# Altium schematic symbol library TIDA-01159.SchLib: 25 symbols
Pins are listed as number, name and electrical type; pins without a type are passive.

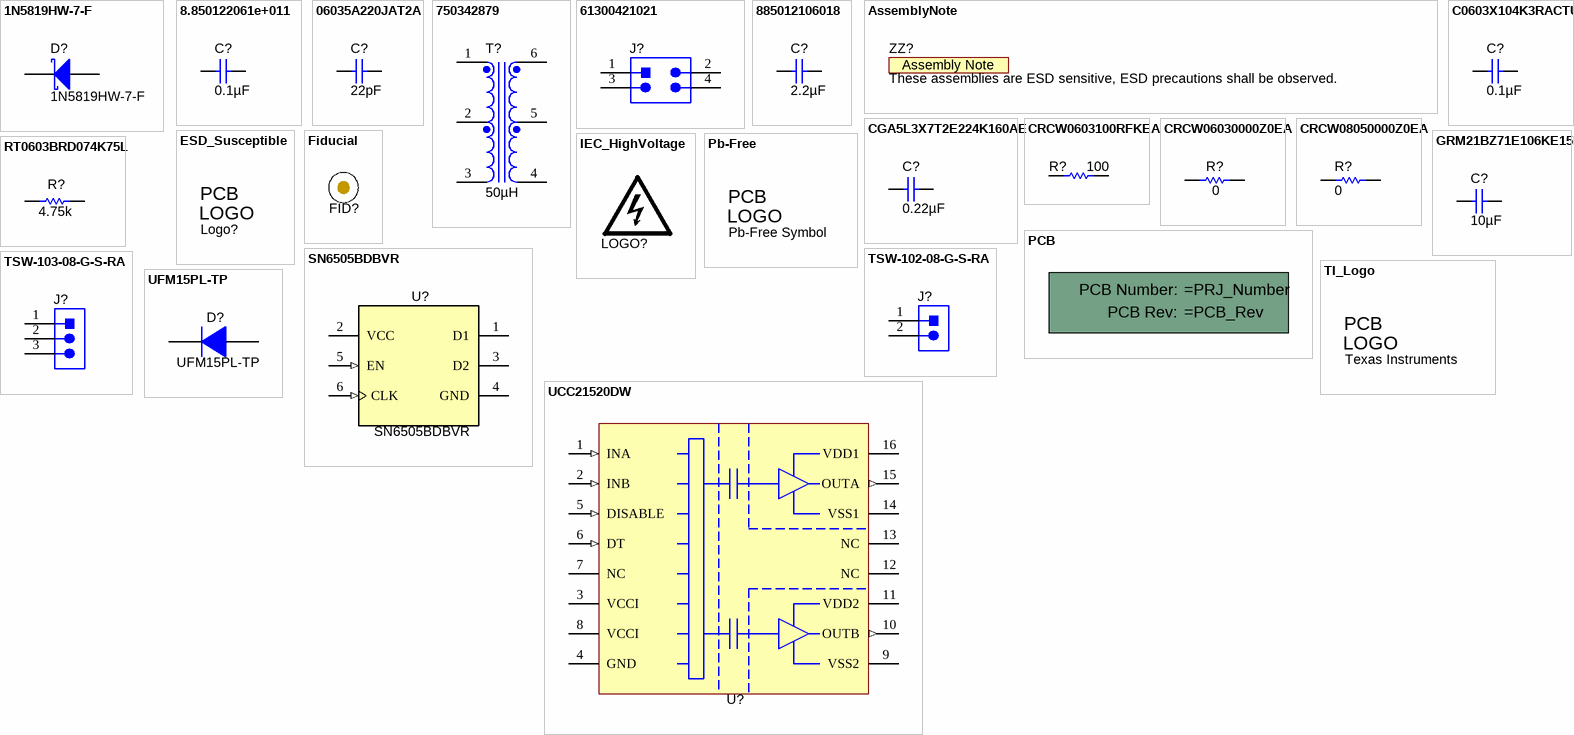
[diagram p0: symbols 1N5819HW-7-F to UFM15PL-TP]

## 1N5819HW-7-F
designator D?
Diode, Schottky, 40 V, 1 A, SOD-123; Manufacturer: Diodes Inc.; U/M: EA; Vf_V: 0.45; Value: 40V; Value1: 1A; Value2: 0.45V; Io_A: 1; Vr_V: 40; TJmax_C: 125; SizeAreaWB_mm2: 13.095; SizeArea_mm2: 6.545; SizeX_mm: 3.85; SizeY_mm: 1.7; SizeZ_mm: 1.35; AEC Category: Q101
signal-integrity model Diode
simulation model DI_1N5819HW
footprint SOD-123
pins: 1 K, 2 A

## 8.850122061e+011
designator C?  ValueDisplayed: 0.1µF  (hidden comment: 8.850122061e+011)
CAP, CERM, 0.1 µF, 50 V, +/- 10%, X7R, 0603; Manufacturer: Wurth Elektronik; Polarized: N; CompType: Capacitor; Value: 0.1uF; U/M: EA; Cap_F: 0.0000001; Tolerance_%: 10; Value1: Unknown; VDC_V: 50; Value2: 50V; TaMin_C: -55; TaMax_C: 125; Cap_Case: 0603; SizeArea_mm2: 1.28; SizeAreaWB_mm2: 4.68; SizeX_mm: 1.6; SizeY_mm: 0.8; SizeZ_mm: 1; AEC Category: Q200
signal-integrity model Cap
simulation model Cap
footprint 0603
footprint 0603M
footprint 0603L
footprint 0603_HV
footprint 0603S
pins: 1, 2

## 06035A220JAT2A
designator C?  ValueDisplayed: 22pF  (hidden comment: 06035A220JAT2A)
CAP, CERM, 22 pF, 50 V, +/- 5%, C0G/NP0, 0603; Manufacturer: AVX; Polarized: N; CompType: Capacitor; Value: 22pF; U/M: EA; Cap_F: 0.000000000022; Tolerance_%: 5; ESR_ohm: 0.259; Value1: 0.259 ohm; VDC_V: 50; Value2: 50V; TaMin_C: -55; TaMax_C: 125; Cap_Case: 0603; SizeArea_mm2: 1.28; SizeAreaWB_mm2: 4.68; SizeX_mm: 1.6; SizeY_mm: 0.8; SizeZ_mm: 1; AEC Category: Q200
signal-integrity model Cap
simulation model Cap
footprint 0603
footprint 0603M
footprint 0603L
footprint 0603_HV
footprint 0603S
pins: 1, 2

## 750342879
designator T?  ValueDisplayed: 50µH  (hidden comment: 750342879)
Transformer, 50 uH, SMT; Manufacturer: Wurth Elektronik; SymbolCreator: Altium; Value: 50uH; Lp: 50
footprint Wurth_750342879
pins: 1, 2, 3, 4, 5, 6

## 61300421021
designator J?  (value not drawn)
Header, 2.54mm, 2x2, Gold, R/A, TH; Manufacturer: Wurth Elektronik; SymbolCreator: a0412235; Pitch_mm: 2.54; Gender: Male; Shrouded: N; Row_Count: 2
footprint Wurth_61300421021
pins: 1, 2, 3, 4

## 885012106018
designator C?  ValueDisplayed: 2.2µF  (hidden comment: 885012106018)
CAP, CERM, 2.2 µF, 16 V, +/- 20%, X5R, 0603; Manufacturer: Wurth Elektronik; Polarized: N; CompType: Capacitor; Value: 2.2uF; U/M: EA; Cap_F: 0.0000022; Tolerance_%: 20; Value1: Unknown; VDC_V: 16; Value2: 16V; TaMin_C: -55; TaMax_C: 85; Cap_Case: 0603; SizeArea_mm2: 1.28; SizeAreaWB_mm2: 4.68; SizeX_mm: 1.6; SizeY_mm: 0.8; SizeZ_mm: 1; AEC Category: Q200
signal-integrity model Cap
simulation model Cap
footprint 0603 (0603 from SM-752 data)
footprint 0603M
footprint 0603L
footprint 0603_HV
footprint 0603S
pins: 1, 2

## AssemblyNote
designator ZZ?, comment These assemblies are ESD sensitive, ESD precautions shall be observed.  (no BOM)
SymbolCreator: codlsc; CompType: AssemblyNote
footprint AssemblyNote

## C0603X104K3RACTU
designator C?  ValueDisplayed: 0.1µF  (hidden comment: C0603X104K3RACTU)
CAP, CERM, 0.1 µF, 25 V, +/- 10%, X7R, 0603; Manufacturer: Kemet; Polarized: N; CompType: Capacitor; Value: 0.1uF; U/M: EA; Cap_F: 0.0000001; Tolerance_%: 10; Value1: Unknown; VDC_V: 25; Value2: 25V; TaMin_C: -55; TaMax_C: 125; Cap_Case: 0603
signal-integrity model Cap
simulation model Cap
footprint 0603
footprint 0603M
footprint 0603L
footprint 0603_HV
footprint 0603S
pins: 1, 2

## CGA5L3X7T2E224K160AE
designator C?  ValueDisplayed: 0.22µF  (hidden comment: CGA5L3X7T2E224K160AE)
CAP, CERM, 0.22 µF, 250 V, +/- 10%, X7T, 1206; Manufacturer: TDK; Polarized: N; CompType: Capacitor; Value: 0.22uF; U/M: EA; Cap_F: 0.00000022; Tolerance_%: 10; Value1: Unknown; VDC_V: 250; Value2: 250V; TaMin_C: -55; TaMax_C: 125; Cap_Case: 1206
signal-integrity model Cap
simulation model Cap
footprint 1206
footprint 1206M
footprint 1206L
pins: 1, 2

## CRCW0603100RFKEA
designator R?  ValueDisplayed: 100  (hidden comment: CRCW0603100RFKEA)
RES, 100, 1%, 0.1 W, 0603; Manufacturer: Vishay-Dale; CompType: Resistor; Value: 100; Value_Code: 100R; Tolerance_%: 1; Power_W: 0.1; Value2: 0.1W; VDC_V: 75; TempCo: 100 ppm/C; EIA_Code: E96; U/M: EA
signal-integrity model Resistor
simulation model Resistor
footprint 0603
footprint 0603M
footprint 0603L
footprint 0603_HV
footprint 0603S
pins: 1, 2

## CRCW06030000Z0EA
designator R?  ValueDisplayed: 0  (hidden comment: CRCW06030000Z0EA)
RES, 0, 5%, 0.1 W, 0603; Manufacturer: Vishay-Dale; CompType: Resistor; Value: 0; Value_Code: 0000; Tolerance_%: 5; Power_W: 0.1; Value2: 0.1W; VDC_V: 75; TempCo: 200 ppm/C; EIA_Code: E24; U/M: EA
signal-integrity model Resistor
simulation model Resistor
footprint 0603
footprint 0603M
footprint 0603L
footprint 0603_HV
footprint 0603S
pins: 1, 2

## CRCW08050000Z0EA
designator R?  ValueDisplayed: 0  (hidden comment: CRCW08050000Z0EA)
RES, 0, 5%, 0.125 W, 0805; Manufacturer: Vishay-Dale; CompType: Resistor; Value: 0; Value_Code: 0000; Tolerance_%: 5; Power_W: 0.125; Value2: 0.125W; VDC_V: 150; TempCo: 200 ppm/C; EIA_Code: E24; U/M: EA; AEC Category: Q200
signal-integrity model Resistor
simulation model Resistor
footprint 0805_HV
footprint 0805_HV1
footprint 0805
footprint 0805M
pins: 1, 2

## ESD_Susceptible
designator Logo?, comment ESD Susceptible  (value not drawn)  (no BOM)
ESD Susceptible Symbol; SymbolCreator: a0412235
footprint ESD_Overlay_Large
footprint ESD_Overlay_Medium
footprint ESD_Overlay_Small

## Fiducial
designator FID?  (value not drawn)
Fiducial mark.  There is nothing to buy or mount.; SymbolCreator: codlsc
footprint Fiducial10-30
footprint Fiducial10-20
footprint Fiducial15-30
footprint Fiducial20-40
footprint Fiducial6.4-20

## GRM21BZ71E106KE15L
designator C?  ValueDisplayed: 10µF  (hidden comment: GRM21BZ71E106KE15L)
CAP, CERM, 10 µF, 25 V, +/- 10%, X7R, 0805; Manufacturer: MuRata; Polarized: N; CompType: Capacitor; Value: 10uF; U/M: EA; Cap_F: 0.00001; Tolerance_%: 10; Value1: Unknown; VDC_V: 25; Value2: 25V; TaMin_C: -55; TaMax_C: 125; Cap_Case: 0805; SizeArea_mm2: 2.5; SizeAreaWB_mm2: 6.75; SizeX_mm: 2; SizeY_mm: 1.25; SizeZ_mm: 1.45; AEC Category: Q200
signal-integrity model Cap
simulation model Cap
footprint 0805_HV
footprint 0805_HV1
footprint 0805
footprint 0805M
footprint 0805L
pins: 1, 2

## IEC_HighVoltage
designator LOGO?, comment DANGER HIGH VOLTAGE  (value not drawn)  (no BOM)
IEC 61010-1 High Voltage Warning; SymbolCreator: a0412235
footprint IEC_HighVoltage_Large
footprint IEC_HighVoltage_Medium
footprint IEC_HighVoltage_Small

## Pb-Free
designator Logo?, comment Pb-Free Symbol  (no BOM)
SymbolCreator: a0412235
footprint Pb-Free_Overlay_Medium
footprint Pb-Free_Overlay_Small

## PCB
designator !PCB?, comment Printed Circuit Board  (value not drawn)  (mechanical)
Manufacturer: Any; SymbolCreator: a0412235; CompType: PCB
1 alternate drawing of the same symbol

## RT0603BRD074K75L
designator R?  ValueDisplayed: 4.75k  (hidden comment: RT0603BRD074K75L)
RES, 4.75 k, 0.1%, 0.1 W, 0603; Manufacturer: Yageo America; CompType: Resistor; Value: 4.75k; Res_ohm: 4750; Value_Code: 4k75; Tolerance_%: 0.1; Value2: 0.1W; VDC_V: 75; TempCo: 25 ppm/C; EIA_Code: E192; U/M: EA
signal-integrity model Resistor
simulation model Resistor
footprint 0603
footprint 0603M
footprint 0603L
footprint 0603_HV
footprint 0603S
pins: 1, 2

## SN6505BDBVR
designator U?
LOW-NOISE 1A TRANSFORMER DRIVERS FOR ISOLATED POWER SUPPLIES, DBV0006A; Alternate PartNumber: SN6505BDBVT; Manufacturer: Texas Instruments; SymbolCreator: Altium; SizeArea_mm2: 8.12; SizeAreaWB_mm2: 14.82; SizeX_mm: 2.8; SizeY_mm: 2.9; SizeZ_mm: 1.45; CompType: IC; U/M: EA
footprint DBV0006A_N
footprint DBV0006A_M
footprint DBV0006A_L
pins: 1 D1 (oc), 2 VCC (power), 3 D2 (oc), 4 GND (power), 5 EN (in), 6 CLK (in)
1 alternate drawing of the same symbol

## TI_Logo
designator Logo?, comment Texas Instruments  (no BOM)
Texas Instrument Corporate Signature; SymbolCreator: codlsc
footprint TI_Stacked_SolderMask_Medium
footprint TI_Stacked_SolderMask_Small
footprint TI_Stacked_Overlay_Medium
footprint TI_Stacked_Overlay_Small
footprint TI_Horizontal_SolderMask_Medium
footprint TI_Horizontal_SolderMask_Small
footprint TI_Horizontal_Overlay_Medium
footprint TI_Horizontal_Overlay_Small
footprint TI_Symbol_SolderMask_Small
footprint TI_Symbol_Overlay_Medium
footprint TI_Symbol_Overlay_Small
footprint TI_Symbol_SolderMask_Medium

## TSW-102-08-G-S-RA
designator J?  (value not drawn)
Header, 100mil, 2x1, Gold, R/A, TH; Manufacturer: Samtec; SymbolCreator: a0412235; Pitch_mm: 2.54; Gender: Male; Shrouded: N; Row_Count: 1; Current_A: 6.3; Voltage_V: 550; Cert_CSA: Y
footprint TSW-102-08-G-S-RA
pins: 1, 2
1 alternate drawing of the same symbol

## TSW-103-08-G-S-RA
designator J?  (value not drawn)
Header, 100mil, 3x1, Gold, R/A, TH; Manufacturer: Samtec; SymbolCreator: a0799628; Pitch_mm: 2.54; Gender: Male; Shrouded: N; Row_Count: 1; Current_A: 6.3; Voltage_V: 550; Cert_CSA: Y
footprint TSW-103-08-G-S-RA
pins: 1, 2, 3
3 alternate drawings of the same symbol

## UCC21520DW
designator U?  (value not drawn)
4A/6A, 5KVrms Dual Isolated-channel Universal Gate Driver, DW0016A; Manufacturer: Texas Instruments; SymbolCreator: a0799628; CompType: IC; U/M: EA
footprint DW0016A_N
footprint DW0016A_M
footprint DW0016A_L
pins: 1 INA (in), 2 INB (in), 3 VCCI (power), 4 GND (power), 5 DISABLE (in), 6 DT (in), 7 NC, 8 VCCI (power), 9 VSS2 (power), 10 OUTB (out), 11 VDD2 (power), 12 NC, 13 NC, 14 VSS1 (power), 15 OUTA (out), 16 VDD1 (power)

## UFM15PL-TP
designator D?
Diode, Ultrafast, 600 V, 1 A, SOD-123FL; Manufacturer: Micro Commercial Components; U/M: EA; Vf_V: 1.7; Value: 600V; Value1: 1A; Value2: 1.7V; Io_A: 1; Vr_V: 600; TJmax_C: 150; SizeAreaWB_mm2: 13.44; SizeArea_mm2: 6.84; SizeX_mm: 3.8; SizeY_mm: 1.8; AEC Category: Q101; AEC Qualified: N
signal-integrity model Diode
footprint SOD-123FL
pins: 1 K, 2 A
